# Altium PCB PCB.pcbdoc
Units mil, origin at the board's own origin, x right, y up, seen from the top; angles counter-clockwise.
Board outline 1800 x 1300 mil, 4 copper layers (Top Layer, Inner1, Inner2, Bottom Layer), stack 62.447 mil thick; 43 components, 24 nets, 128 pads, 70 vias.
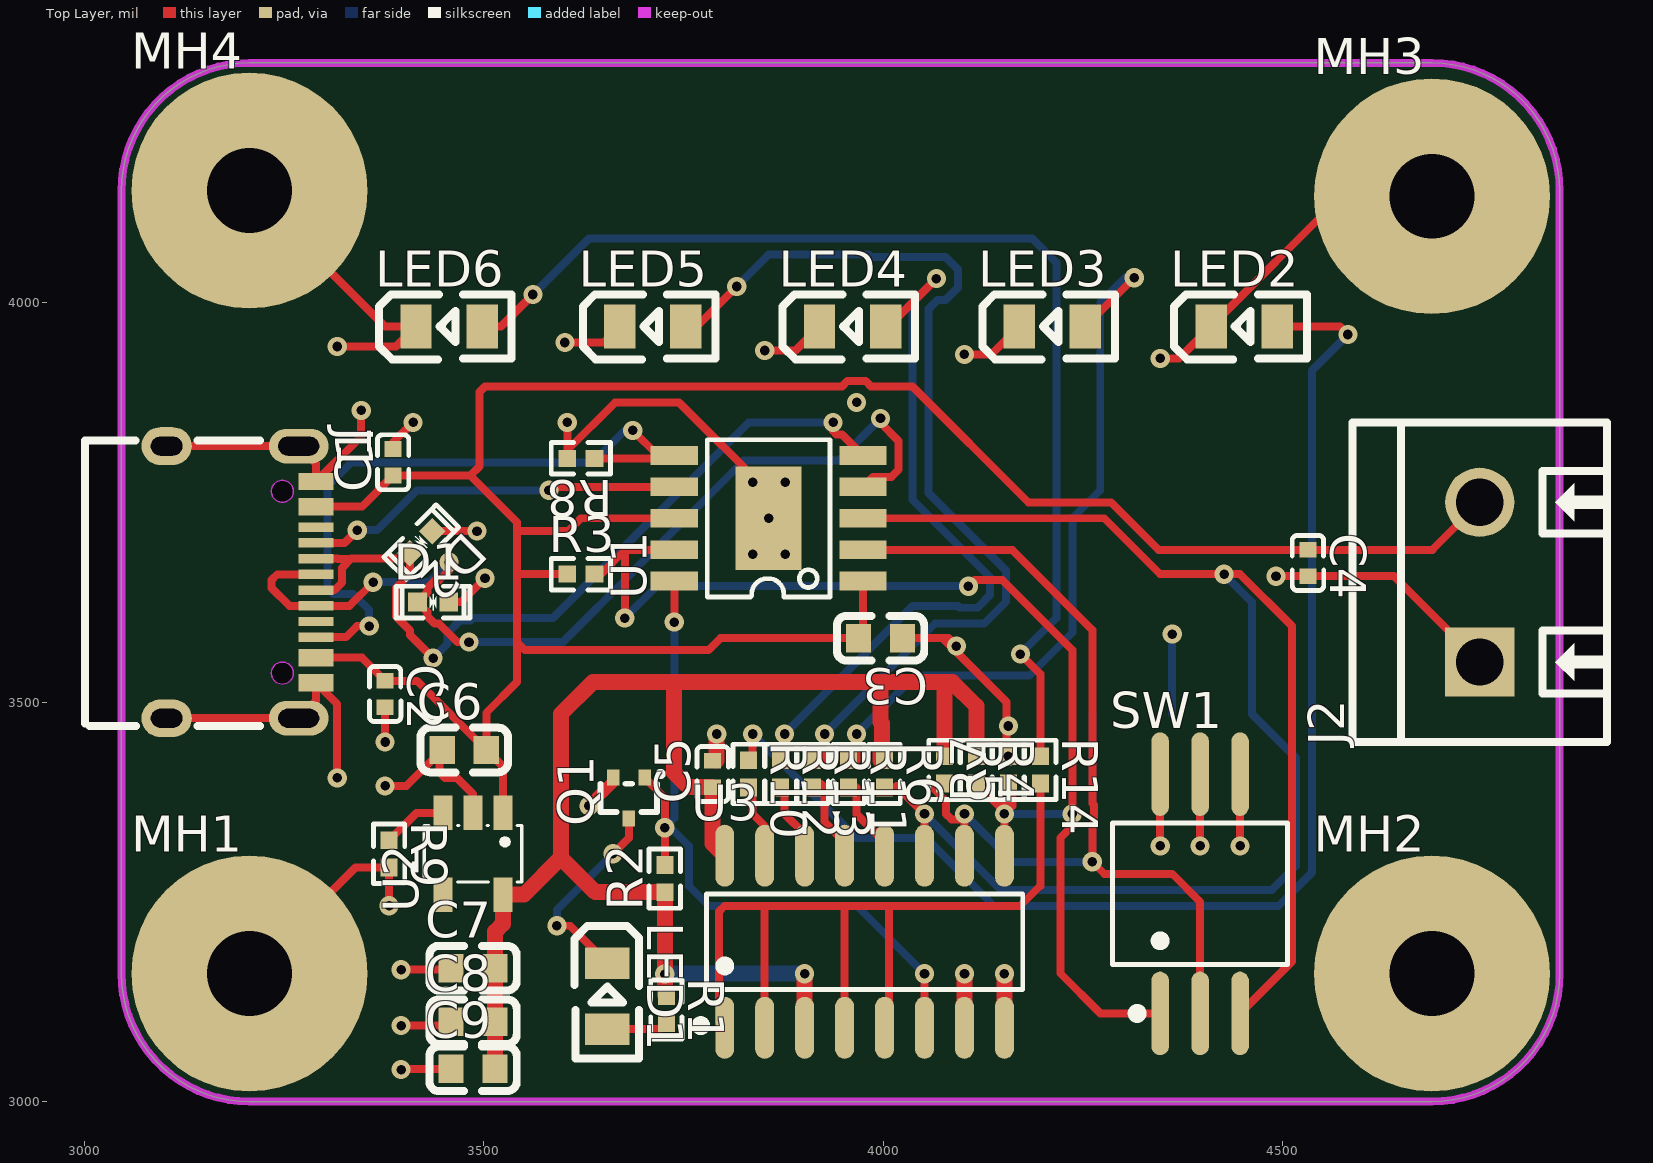
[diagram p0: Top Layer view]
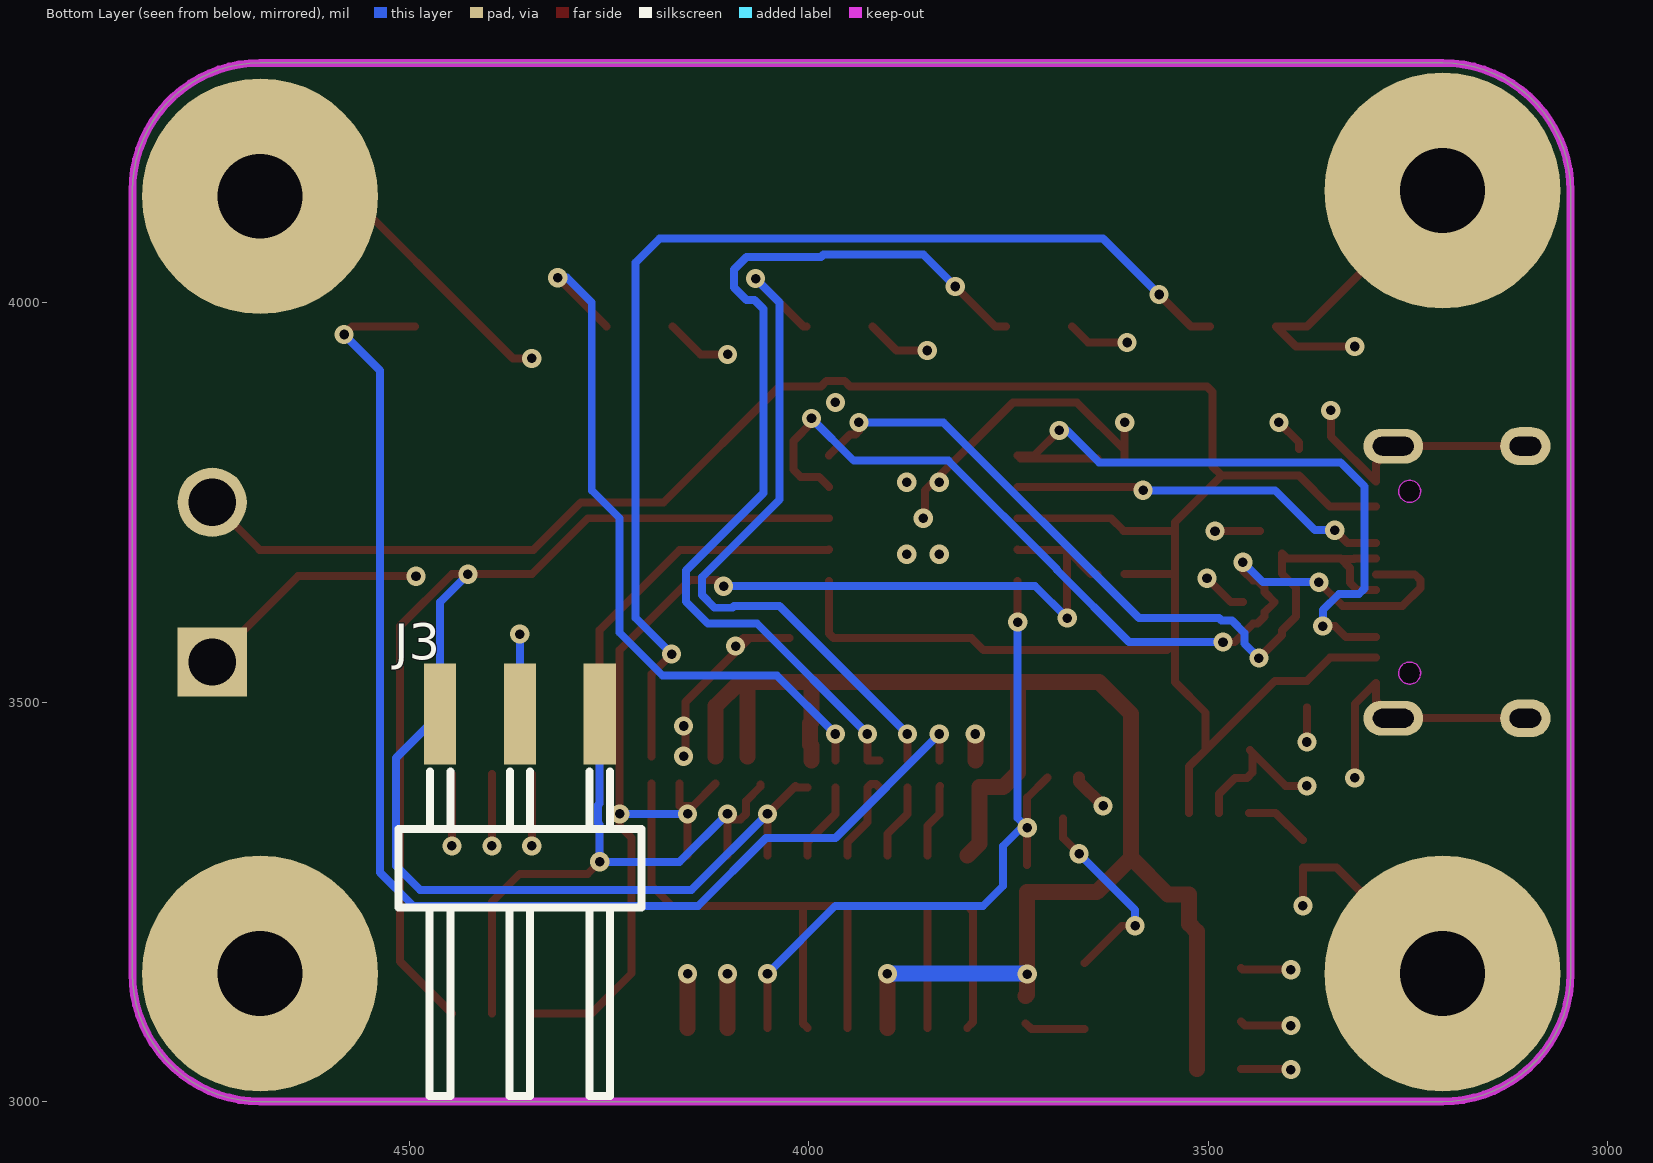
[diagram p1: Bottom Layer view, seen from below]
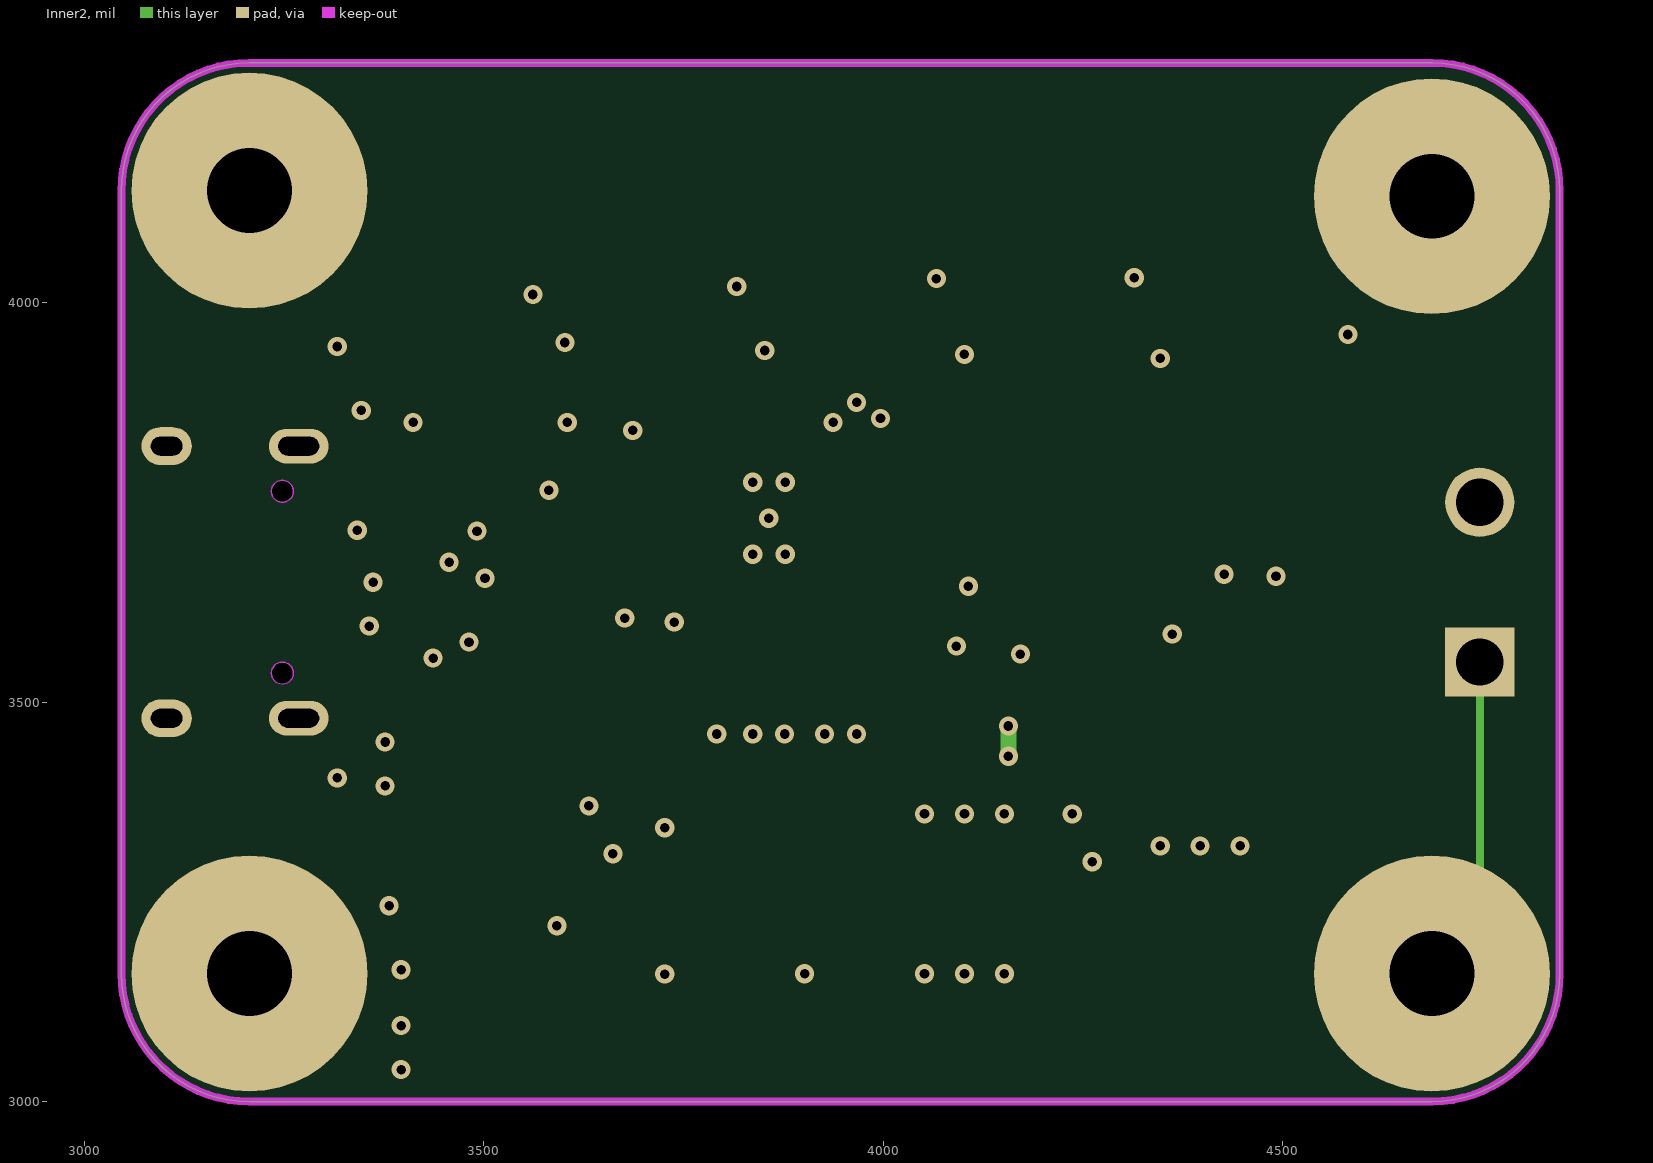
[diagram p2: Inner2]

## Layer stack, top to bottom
Top Layer: signal copper 1.378
Dielectric1: surface 8.283, 7628 RC49% 8.6mil, Dk 0
Inner1: signal copper 0.598
Dielectric2: surface 41.929, 1.1mm H/HOZ Copper, Dk 0
Inner2: signal copper 0.598
Dielectric3: surface 8.283, 7628 RC49% 8.6mil, Dk 0
Bottom Layer: signal copper 1.378

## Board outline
3206.88,4300 ccw(c3206.88,4140) 3046.88,4140 3046.88,3160 ccw(c3206.88,3160) 3206.88,3000 4686.88,3000 ccw(c4686.88,3160) 4846.88,3160 4846.88,4140 ccw(c4686.88,4140) 4686.88,4300

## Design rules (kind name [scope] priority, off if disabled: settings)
BoardOutlineClearance copperThickness1oz [All] p0: genericclearance=10 ignorepadtopadclearanceinfootprint=FALSE except(0: Arc-SplitContinuation Track-SplitContinuation SMDPad-SplitContinuation THPad-SplitContinuation Via-SplitContinuation Fill-SplitContinuation Poly-SplitContinuation Region-SplitContinuation Text-SplitContinuation)
BoardOutlineClearance copperThickness2oz [All] p0: genericclearance=10 ignorepadtopadclearanceinfootprint=FALSE except(0: Arc-SplitContinuation Track-SplitContinuation SMDPad-SplitContinuation THPad-SplitContinuation Via-SplitContinuation Fill-SplitContinuation Poly-SplitContinuation Region-SplitContinuation Text-SplitContinuation)
BoardOutlineClearance USBC_Clearance [All] p0: genericclearance=10 ignorepadtopadclearanceinfootprint=FALSE except(0: Arc-SplitContinuation Track-SplitContinuation SMDPad-SplitContinuation THPad-SplitContinuation Via-SplitContinuation Fill-SplitContinuation Poly-SplitContinuation Region-SplitContinuation Text-SplitContinuation)
BoardOutlineClearance otherClearance [All] p0: genericclearance=10 ignorepadtopadclearanceinfootprint=FALSE except(0: Arc-SplitContinuation Track-SplitContinuation SMDPad-SplitContinuation THPad-SplitContinuation Via-SplitContinuation Fill-SplitContinuation Poly-SplitContinuation Region-SplitContinuation Text-SplitContinuation)
Clearance copperThickness1oz [All] p1: gap=7 ignorepadtopadclearanceinfootprint=FALSE
Clearance copperThickness2oz [All] p1: gap=7 ignorepadtopadclearanceinfootprint=FALSE
Clearance USBC_Clearance [All] p1: gap=7 ignorepadtopadclearanceinfootprint=FALSE
Clearance otherClearance [All] p1: gap=7 ignorepadtopadclearanceinfootprint=FALSE
DiffPairsRouting differentialPair [All] p1: maxuncoupledlength=10 minlimit=6 maxlimit=Infinity mostfreqgap=6 toplayer_minwidth=6.2 toplayer_prefwidth=8 toplayer_maxwidth=10 bottomlayer_minwidth=6.2 bottomlayer_prefwidth=8 bottomlayer_maxwidth=10 midlayer1_minwidth=6.2 midlayer1_prefwidth=8 midlayer1_maxwidth=10 midlayer2_minwidth=6.2 midlayer2_prefwidth=8 midlayer2_maxwidth=10
PasteMaskExpansion pasteMaskExpansion [All] p1: expansion=0
PlaneConnect innerPlane [All] p1: planeconnectstyle=Relief reliefexpansion=20 reliefentries=4 reliefconductorwidth=10 reliefairgap=10
PolygonConnect copperRegion [All] p1: connectstyle=Relief reliefentries=4 reliefconductorwidth=10 polygonreliefangle="90 Angle" airgapwidth=10
RoutingVias viaSize [All] p1: viastyle="Through Hole" holewidth=12.0078 minholewidth=11.811 maxholewidth=248.0314 width=12.0078 minwidth=11.811 maxwidth=248.0314
SolderMaskExpansion solderMaskExpansion [IsVia] p1: useseparateexpansions=TRUE expansion=-1000 expansionbottom=-1000
SolderMaskExpansion solderMaskExpansion [All] p2: useseparateexpansions=TRUE expansion=2 expansionbottom=2
Width copperThickness1oz [All] p1: maxlimit=100 minlimit=10 preferedwidth=10
Width copperThickness2oz [All] p1: maxlimit=100 minlimit=8 preferedwidth=10

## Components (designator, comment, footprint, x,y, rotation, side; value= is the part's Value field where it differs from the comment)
C1 "100nF" C0402 3386.88,3800 r90 top
C2 "100nF" C0402 3376.88,3510 r270 top
C3 "1uF" C0603 3996.88,3580 r180 top
C4 "100nF" C0402 4531.88,3674 r270 top
C5 "100nF" C0402 3786.88,3410 r90 top
C6 "1uF" C0603 3475.88,3440 r0 top
C7 "1uF" C0603 3486.88,3167 r0 top
C8 "1uF" C0603 3486.88,3100.02 r0 top
C9 "1uF" C0603 3486.88,3041 r0 top
D1 "GG0402052R542P" D0402-BI 3436.88,3625 r0 top
D2 "GG0402052R542P" D0402-BI 3421.88,3700 r225 top
J1 "TYPE-C 16PIN 2MD(073)" USB-C-SMD_TYPE-C-16PIN-2MD-073 3196.88,3650 r270 top
J2 "MKDSN 1,5/ 2-5,08" CONN-TH_2P-P5.08_1729128 4746.88,3650 r90 top
J3 "HX PZ2.54-1x3P WT" HDR-SMD_3P-P2.54-H-M_KH-2.54PH-1X3P-L13.5-WT 4361.89,3485.01 r180 bottom
LED1 "KT-0805R" LED0805-R-RD 3654.88,3132 r270 top
LED2 "KT-0805G" LED0805-R-RD 4451.88,3970 r0 top
LED3 "KT-0805G" LED0805-R-RD 4211.88,3970 r0 top
LED4 "KT-0805G" LED0805-R-RD 3961.88,3970 r0 top
LED5 "KT-0805G" LED0805-R-RD 3711.88,3970 r0 top
LED6 "KT-0805G" LED0805-R-RD 3456.88,3970 r0 top
MH1 "" MH_7.5MMx2.7MM 3206.88,3160 r0 top
MH2 "" MH_7.5MMx2.7MM 4686.88,3160 r0 top
MH3 "" MH_7.5MMx2.7MM 4686.88,4133 r0 top
MH4 "" MH_7.5MMx2.7MM 3206.88,4140 r0 top
Q1 "2N7002T-7-F" SOT-523-3_L1.6-W0.8-P1.00-LS1.6-BR 3681.88,3380 r90 top
R1 "1kΩ" R0402 3728.88,3115 r270 top
R2 "10kΩ" R0402 3726.88,3279 r90 top
R3 "100kΩ" R0402 3621.88,3660 r0 top
R4 "10kΩ" R0402 4116.88,3415 r270 top
R5 "10kΩ" R0402 4076.88,3415 r270 top
R6 "10kΩ" R0402 4001.88,3410 r270 top
R7 "6.8kΩ" R0402 4156.88,3415 r90 top
R8 "1kΩ" R0402 3621.88,3805 r180 top
R9 "10kΩ" R0402 3381.88,3310 r270 top
R10 "1kΩ" R0402 3831.88,3410 r270 top
R11 "1kΩ" R0402 3956.88,3410 r270 top
R12 "1kΩ" R0402 3871.88,3410 r270 top
R13 "1kΩ" R0402 3911.88,3410 r270 top
R14 "1kΩ" R0402 4196.88,3415 r270 top
SW1 "DSHP03TS-S" SW-SMD_DSHP03TS-S 4396.87,3259.98 r0 top
U1 "CH224A" ESSOP-10_L4.9-W3.9-P1.0-LS6.0-TL-EP 3856.88,3730 r90 top
U2 "TPS70933DBVR" SOT-23-5_L3.0-W1.7-P0.95-LS2.8-BR 3486.87,3310.01 r90 top
U3 "MC14051BDR2G" SOIC-16_L9.9-W3.9-P1.27-LS6.0-BL 3976.93,3200 r0 top

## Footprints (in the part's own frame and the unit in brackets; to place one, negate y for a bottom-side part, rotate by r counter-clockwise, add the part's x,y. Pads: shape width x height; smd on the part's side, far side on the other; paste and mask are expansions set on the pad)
C0402 [mm]
  rect 0.5x0.54 smd paste+0 mask+0.051: 1(-0.42,0) 2(0.42,0)
  silkscreen extent -0.87,-0.5 0.87,0.5
C0603 [mm]
  rect 0.8x0.9 smd: 1(-0.7,0) 2(0.7,0)
  silkscreen extent -1.39,-0.71 1.39,0.71
CONN-TH_2P-P5.08_1729128 [mm]
  rect 2.2x2.2 hole 1.5: 1(-2.54,0)
  round 2.2 hole 1.5: 2(2.54,0)
  silkscreen extent -5.08,-4.05 5.08,4.05
D0402-BI [mm]
  rect 0.6x0.6 smd paste-100 mask+0.051: 1(-0.5,0) 2(0.5,0)
  silkscreen extent -1.18,-0.5 1.17,0.51
ESSOP-10_L4.9-W3.9-P1.0-LS6.0-TL-EP [mm]
  rect 0.6x1.5 smd paste+0 mask+0.05: 1(-2,-3) 2(-1,-3) 3(0,-3) 4(1,-3) 5(2,-3) 6(2,3) 7(1,3) 8(0,3) 9(-1,3) 10(-2,3)
  rect 3.3x2.1 smd paste+0 mask+0.05: 11(0,0)
  silkscreen extent -2.5,-1.95 2.5,1.95
HDR-SMD_3P-P2.54-H-M_KH-2.54PH-1X3P-L13.5-WT [mm]
  rect 1.02x3.2 smd paste+0 mask+0.05: 1(-2.54,0) 2(0,0) 3(2.54,0)
  silkscreen extent -3.86,-12.15 3.87,-1.83
LED0805-R-RD [mm]
  rect 1x1.4 smd: 1(1.05,0) 2(-1.05,0)
  silkscreen extent -2.22,-1.04 1.99,1.01
MH_7.5MMx2.7MM [mm]
  round 7.5 hole 2.7: 1(0,0)
R0402 [mm]
  rect 0.566x0.54 smd paste-100 mask+0.051: 1(-0.433,0) 2(0.433,0)
  silkscreen extent -0.94,-0.5 0.94,0.5
SOIC-16_L9.9-W3.9-P1.27-LS6.0-BL [mil]
  oval 23.7x77.6 smd: 1(-175,-107.7) 2(-125,-107.7) 3(-75,-107.7) 4(-25,-107.7) 5(25,-107.7) 6(75,-107.7) 7(125,-107.7) 8(175,-107.7) 9(175,107.7) 10(125,107.7) 11(75,107.7) 12(25,107.7) 13(-25,107.7) 14(-75,107.7) 15(-125,107.7) 16(-175,107.7)
  silkscreen extent -211,-111 198,60
SOT-23-5_L3.0-W1.7-P0.95-LS2.8-BR [mm]
  rect 1.1x0.6 smd: 1(1.3,-0.95) 2(1.3,0) 3(1.3,0.95) 4(-1.3,0.95) 5(-1.3,-0.95)
  silkscreen extent -0.9,-1.55 0.9,1.55
SOT-523-3_L1.6-W0.8-P1.00-LS1.6-BR [mm]
  rect 0.51x0.4 smd: 1(0.65,-0.5) 2(0.65,0.5) 3(-0.65,0)
  silkscreen extent -0.45,-1.08 0.83,0.9
SW-SMD_DSHP03TS-S [mm]
  oval 0.56x2.655 smd: 1(-1.27,-3.803) 2(0,-3.803) 3(1.27,-3.803) 4(1.27,3.803) 5(0,3.803) 6(-1.27,3.803)
  silkscreen extent -2.78,-3.95 2.78,2.25
USB-C-SMD_TYPE-C-16PIN-2MD-073 [mm]
  oval 1.1x1.9 hole 0.6 slot 1.3 at 90 deg paste+0 mask+0.05: 13(-4.325,1.825) 14(4.325,1.825)
  oval 1.2x1.6 hole 0.6 slot 1 at 90 deg paste+0 mask+0.05: 13(-4.325,-2.375) 14(4.325,-2.375)
  rect 0.55x1.1 smd paste+0 mask+0.05: A1B12(-3.2,2.375) A4B9(-2.4,2.375) B1A12(3.2,2.375) B4A9(2.4,2.375)
  rect 0.3x1.1 smd paste+0 mask+0.05: A5(-1.25,2.375) A6(-0.25,2.375) A7(0.25,2.375) A8(1.25,2.375) B5(1.75,2.375) B6(0.75,2.375) B7(-0.75,2.375) B8(-1.75,2.375)
  Board Outline Layer circle w0.003: c-2.89,1.305 r0.35
  Board Outline Layer circle w0.003: c2.89,1.305 r0.35
  Board Outline Layer region: -2.89,1.655 -2.738,1.62 -2.616,1.523 -2.549,1.383 -2.549,1.227 -2.616,1.087 -2.738,0.99 -2.89,0.955 -2.89,0.955 -3.042,0.99 -3.164,1.087 -3.231,1.227 -3.231,1.383 -3.164,1.523 -3.042,1.62 -2.89,1.655
  Board Outline Layer region: -2.89,1.655 -2.812,1.646 -2.738,1.62 -2.672,1.579 -2.616,1.523 -2.575,1.457 -2.549,1.383 -2.54,1.305 -2.549,1.227 -2.575,1.153 -2.616,1.087 -2.672,1.031 -2.738,0.99 -2.812,0.964 -2.89,0.955 -2.968,0.964 -3.042,0.99 -3.108,1.031 -3.164,1.087 -3.205,1.153 -3.231,1.227 -3.24,1.305 -3.231,1.383 -3.205,1.457 -3.164,1.523 -3.108,1.579 -3.042,1.62 -2.968,1.646
  Board Outline Layer region: 2.89,1.655 3.042,1.62 3.164,1.523 3.231,1.383 3.231,1.227 3.164,1.087 3.042,0.99 2.89,0.955 2.89,0.955 2.738,0.99 2.616,1.087 2.549,1.227 2.549,1.383 2.616,1.523 2.738,1.62 2.89,1.655
  Board Outline Layer region: 2.89,1.655 2.968,1.646 3.042,1.62 3.108,1.579 3.164,1.523 3.205,1.457 3.231,1.383 3.24,1.305 3.231,1.227 3.205,1.153 3.164,1.087 3.108,1.031 3.042,0.99 2.968,0.964 2.89,0.955 2.812,0.964 2.738,0.99 2.672,1.031 2.616,1.087 2.575,1.153 2.549,1.227 2.54,1.305 2.549,1.383 2.575,1.457 2.616,1.523 2.672,1.579 2.738,1.62 2.812,1.646
  Multi-Layer board cut-out: -2.89,1.655 -2.738,1.62 -2.616,1.523 -2.549,1.383 -2.549,1.227 -2.616,1.087 -2.738,0.99 -2.89,0.955 -2.89,0.955 -3.042,0.99 -3.164,1.087 -3.231,1.227 -3.231,1.383 -3.164,1.523 -3.042,1.62 -2.89,1.655
  Multi-Layer board cut-out: 2.89,1.655 3.042,1.62 3.164,1.523 3.231,1.383 3.231,1.227 3.164,1.087 3.042,0.99 2.89,0.955 2.89,0.955 2.738,0.99 2.616,1.087 2.549,1.227 2.549,1.383 2.616,1.523 2.738,1.62 2.89,1.655
  silkscreen extent -4.5,-4.97 4.57,0.6

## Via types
v1: diameter 24.02, hole 12, Top Layer to Bottom Layer, 70 vias

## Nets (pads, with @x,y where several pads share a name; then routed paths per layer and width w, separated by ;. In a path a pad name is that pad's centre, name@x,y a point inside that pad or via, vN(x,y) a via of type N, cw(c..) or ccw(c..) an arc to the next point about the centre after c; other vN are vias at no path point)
$1N47: LED1.1 R1.2 | length 77
  Top Layer w10: LED1.1 3721.57,3090.65 R1.2
$1N48: LED1.2 Q1.3 | length 254
  Top Layer w10: v1(3591.88,3220) 3608.23,3220 LED1.2 ; v1(3661.88,3310) 3681.89,3330.01 Q1.3
  Bottom Layer w10: v1(3591.88,3220) 3591.88,3240 v1(3661.88,3310)
$1N55: LED2.1 R10.1 | length 1624
  Top Layer w10: R10.1@3836.88,3427.04 v1(3836.88,3460) ; LED2.1 4571.88,3970 v1(4581.88,3960)
  Bottom Layer w10: v1(3836.88,3460) 3966.88,3330 4053.64,3330 4138.64,3245 4495.17,3245 4536.88,3286.72 4536.88,3915 v1(4581.88,3960)
$1N56: LED3.1 R11.1 | length 925
  Top Layer w10: R11.1@3966.88,3427.04 v1(3966.88,3460) ; LED3.1 v1(4314.35,4031.11)
  Bottom Layer w10: v1(3966.88,3460) 4039.88,3532.99 4183.07,3532.99 4236.88,3586.81 4236.88,3730 4271.88,3765 4271.88,4000 4303,4031.11 v1(4314.35,4031.11)
$1N57: LED4.1 R12.1 | length 900.9
  Top Layer w10: R12.1@3876.88,3427.04 v1(3876.88,3460) ; LED4.1 4006.88,3970 v1(4066.88,4030)
  Bottom Layer w10: v1(3876.88,3460) 4036.88,3620 4093.69,3620 4095.7,3617.99 4118.07,3617.99 4133.89,3633.81 4133.89,3656.19 4036.88,3753.19 4036.88,4000 v1(4066.88,4030)
$1N58: LED5.1 R13.1 | length 1206.2
  Top Layer w10: LED5.1 3766.88,3970 v1(3816.88,4020) ; R13.1 3926.88,3427.04 v1(3926.88,3460)
  Bottom Layer w10: v1(3816.88,4020) 3856.88,4060 3981.88,4060 3984.88,4057.01 4078.07,4057.01 4093.89,4041.19 4093.89,4018.81 4078.07,4002.99 4068.16,4002.99 4056.88,3991.72 4056.88,3761.48 4153.89,3664.47 4153.89,3625.53 4126.36,3597.99 4064.88,3597.99 v1(3926.88,3460)
$1N59: LED6.1 R14.1 | length 1423.6
  Top Layer w10: LED6.1 3521.88,3970 v1(3561.88,4010) ; v1(4171.88,3560) 4196.88,3535 R14.1
  Bottom Layer w10: v1(3561.88,4010) 3631.88,4080 4186.88,4080 4216.88,4050 4216.88,3605 v1(4171.88,3560)
$1N79: R10.2 U3.15 | length 93.9
  Top Layer w10: R10.2@3835.88,3394.96 3836.88,3393.96 3836.88,3360 3851.93,3344.95 U3.15
$1N80: R11.2 U3.12 | length 99.8
  Top Layer w10: R11.2@3966.88,3392.96 3966.88,3360 4001.93,3324.95 U3.12
$1N81: R12.2 U3.14 | length 95.6
  Top Layer w10: R12.2@3876.88,3392.96 3876.88,3360 3901.93,3334.95 U3.14
$1N82: R13.2 U3.13 | length 114.3
  Top Layer w10: R13.2 3916.28,3397.35 3922.49,3397.35 3926.88,3392.96 3926.88,3350 3951.93,3324.95 U3.13
$1N83: R14.2 U3.1 U3.2 U3.4 U3.5 | length 1152.8
  Top Layer w10: U3.1 3794.81,3099.41 3794.81,3237.93 3801.88,3245 3850.92,3245 ; U3.2 3851.93,3243.99 3850.92,3245 ; U3.4 3951.93,3244.73 3951.66,3245 ; U3.5 4007.46,3097.83 4007.46,3245 ; R14.2 4196.88,3270 4171.88,3245 4007.46,3245 ; 3850.92,3245 3951.66,3245 ; 3951.66,3245 4007.46,3245
+3V3: C5.1 C7.2 C8.2 C9.2 R1.1 R2.1 R4.1 R5.1 R6.1 U2.5 U3.3 U3.16 | length 2081.7
  Top Layer w20: C9.2 C8.2 C7.2 3514.44,3212.56 3524.27,3222.39 U2.5 3550.71,3258.82 3596.88,3305 ; R1.1 3726.88,3134.04 v1(3726.88,3159.51) R2.1 3639.92,3261.96 3596.88,3305 ; U3.16 3786.88,3322.74 C5.1 3756.88,3393.46 3738.61,3411.73 3738.61,3523.22 3736.84,3525 ; U3.3 v1(3901.93,3160) ; R6.1@3996.88,3427.04 3996.88,3444.73 3998.89,3446.74 3998.89,3473.26 3996.88,3475.27 3996.88,3524.62 3996.5,3525 ; R5.1 4076.88,3524.52 4076.41,3525 ; R4.1 4116.88,3495 4086.88,3525 4076.41,3525 ; 3596.88,3305 3596.88,3485 3636.88,3525 3736.84,3525 ; 3736.84,3525 3996.5,3525 ; 3996.5,3525 4076.41,3525
  Bottom Layer w20: v1@3726.88,3160 v1(3901.93,3160)
+V_USB: C1.1 C2.1 C3.2 C4.1 C6.2 J1.A4B9 J1.B4A9 J2.2 R3.1 U1.1 U1.8 U2.1 | length 3198.7
  Top Layer w10: J1.B4A9 3347.92,3555.51 C2.1 3416.9,3526.54 C6.2 ; J1.A4B9 3347.91,3744.49 C1.1 3483.42,3783.46 ; U2.1 3524.27,3419.17 C6.2 ; R3.1 3543.42,3660 3541.88,3661.54 ; U1.8 3621.88,3730 3606.12,3714.24 3541.88,3714.24 ; U1.1 3975,3585.68 C3.2 3796.88,3580 3781.88,3565 3551.62,3565 3541.88,3574.74 ; J2.2 4687.42,3690.54 C4.1 4344.63,3690.54 4285.17,3750 4181.88,3750 4036.88,3895 3985.08,3895 3978.07,3902.01 3955.7,3902.01 3948.69,3895 3501.88,3895 3494.81,3887.93 3494.81,3794.85 3483.42,3783.46 ; 3483.42,3783.46 3541.88,3725 3541.88,3714.24 ; C6.2 3503.44,3486.56 3541.88,3525 3541.88,3574.74 ; 3541.88,3574.74 3541.88,3661.54 ; 3541.88,3661.54 3541.88,3714.24
CC1: J1.A5 U1.7 | length 477.4
  Top Layer w10: J1.A5 3326.09,3699.2 v1(3341.88,3715) ; v1(3581.88,3765) 3586.26,3769.37 U1.7
  Bottom Layer w10: v1(3341.88,3715) 3366.88,3715 3416.88,3765 v1(3581.88,3765)
CC2: J1.B5 R8.1 U1.6 | length 860.8
  Top Layer w10: J1.B5 3327.98,3581.09 3341.88,3595 v1(3356.88,3595) ; R8.1 3735.04,3805 U1.6 3718.14,3808.74 v1(3686.88,3840)
  Bottom Layer w10: v1(3356.88,3595) 3356.88,3615 3336.88,3635 3311.88,3635 3304.81,3642.07 3304.81,3770 3334.81,3800 3636.88,3800 3676.88,3840 v1(3686.88,3840)
CFG1: R3.2 R4.2 R7.1 SW1.1 U1.9 U3.9 | length 1591.8
  Top Layer w10: R3.2 3646.88,3660 3676.88,3690 ; v1(3676.88,3605) 3676.88,3690 ; U1.9 3738.14,3690 3676.88,3690 ; v1(4106.88,3645) 4114.38,3652.5 4149.38,3652.5 4236.88,3565 v1(4236.88,3360) 4236.88,3345 4221.88,3330 4221.88,3160.55 4272.16,3110.28 SW1.1 ; R4.2 4144.89,3369.95 4161.88,3369.95 R7.1@4161.88,3397.96 ; U3.9 v1(4151.93,3360)
  Bottom Layer w10: v1(3676.88,3605) 3716.88,3645 v1(4106.88,3645) ; v1(4151.93,3360) v1(4236.88,3360)
CFG2_SCL: J3.3 R5.2 SW1.2 U1.2 U3.10 | length 1412.4
  Top Layer w10: U1.2 3975.63,3690 4161.88,3690 4261.88,3590 4261.88,3373.19 4263.89,3371.19 4263.89,3348.81 4261.88,3346.81 v1(4261.88,3300) 4276.88,3285 4361.88,3285 4396.87,3250.02 SW1.2 ; 4060.88,3396.96 4060.88,3393.98 4078.94,3375.93 4078.94,3360 4085.67,3353.27 4095.19,3353.27 v1(4101.93,3360) U3.10
  Bottom Layer w10: v1(4101.93,3360) 4161.93,3300 v1(4261.88,3300) 4261.89,3346.82 4263.89,3348.81 4263.89,3371.19 4261.89,3373.18 J3.3
CFG3_SDA: J3.1 R6.2 SW1.3 U1.3 U3.11 | length 2141.2
  Top Layer w10: U1.3 4276.88,3730 4346.88,3660 v1(4426.88,3660) 4446.88,3660 4511.88,3595 4511.88,3175.29 SW1.3 ; R6.2 4014.8,3392.96 4016.88,3395.05 v1(4051.93,3360) U3.11
  Bottom Layer w10: v1(4051.93,3360) 4146.93,3265 4486.88,3265 4516.88,3295 4516.88,3430.02 J3.1 4461.89,3624.99 v1(4426.88,3660)
EN_3V3: R9.1 U2.3 | length 81.7
  Top Layer w10: R9.1 3416.04,3361.19 U2.3
GND: C1.2 C2.2 C3.1 C4.2 C5.2 C6.1 C7.1 C8.1 C9.1 D1.2 D2.1 J1.13 J1.14 J1.A1B12 J1.B1A12 J2.1 J3.2 LED2.2 LED3.2 LED4.2 LED5.2 LED6.2 MH1.1 MH2.1 MH3.1 MH4.1 Q1.2 R7.2 R8.2 R9.2 SW1.4 SW1.5 SW1.6 U1.11 U2.2 U3.7 U3.8 | length 4637.6
  Top Layer w10: J1.14@3103.38,3479.72 3268.74,3479.72 3290.39,3501.37 J1.B1A12 3316.88,3497.52 v1(3316.88,3405) ; J1.13@3103.38,3820.27 3268.74,3820.27 3290.39,3798.62 J1.A1B12 3346.88,3832.48 v1(3346.88,3865) ; MH1.1 3339.84,3292.96 R9.2 v1(3381.88,3245) ; MH4.1 3376.89,3970 LED6.2 3390.53,3945 v1(3316.88,3945) ; v1(3376.88,3395) 3403.32,3395 C6.1@3444.81,3436.49 ; v1(3376.88,3450) C2.2 ; C1.2 3386.88,3825 v1(3411.88,3850) ; v1(3396.88,3040) 3397.88,3041 C9.1 ; v1(3396.88,3095) 3454.3,3095 C8.1 ; v1(3396.88,3165) 3457.32,3165 C7.1 ; D2.1 v1(3491.88,3713.92) ; C6.1 C6.1@3444.81,3436.49 ; D1.2 3471.88,3625 v1(3501.88,3655) ; U2.2 3486.87,3385.01 3466.88,3405 3451.88,3405 3444.81,3412.07 C6.1@3444.81,3436.49 ; v1(3601.88,3950) 3650.53,3950 LED5.2 ; R8.2 R8.2@3604.84,3815 ; v1(3604.84,3850) R8.2@3604.84,3815 ; v1(3851.88,3940) 3890.53,3940 LED4.2 ; v1(3856.88,3730) 3854.84,3732.04 3854.84,3765 3744.84,3875 3664.84,3875 R8.2@3604.84,3815 ; v1(4091.88,3570) 4081.88,3580 C3.1 4074.44,3580 4154.44,3500 4154.44,3434.48 v1(4156.88,3432.04) ; v1(4101.88,3935) 4135.53,3935 LED3.2 ; v1(4346.88,3320) SW1.6 ; v1(4346.88,3930) 4370.53,3930 LED2.2 4573.54,4133 MH3.1 ; v1(4396.87,3320) SW1.5 ; v1(4446.88,3320) SW1.4 ; v1(4491.88,3657.46) C4.2 4639.42,3657.46 J2.1
  Top Layer w15: v1(3631.88,3370) 3662.2,3400.32 Q1.2
  Top Layer w20: C5.2@3791.88,3426.54 v1(3791.88,3460) ; U3.7 v1(4101.93,3160) ; U3.8 v1(4151.93,3160)
  Inner2 w10: MH2.1 4746.88,3220 J2.1
  Inner2 w20: v1(4156.88,3432.04) v1(4156.88,3470)
  Bottom Layer w10: J3.2 v1(4361.89,3585)
  other v1: 3836.88,3685 3877.75,3684.9 3836.88,3775 3877.75,3775 3966.88,3875
PG: Q1.1 R2.2 U1.10 U3.6 | length 931.3
  Top Layer w10: Q1.1 3726.88,3380.28 v1(3726.88,3342.66) R2.2 ; v1(3738.78,3600) U1.10 ; U3.6 v1(4051.93,3160)
  Bottom Layer w10: v1(3738.78,3600) 3738.78,3354.55 v1(3726.88,3342.66) 3734.23,3342.66 3756.88,3320 3756.88,3270 3781.98,3244.9 3967.02,3244.9 v1(4051.93,3160)
USB_N: D2.2 J1.A7 J1.B7 U1.5 | length 1040.5
  Top Layer w10: J1.A7 3313.81,3640.16 3323.04,3649.38 3323.04,3667.87 3334.37,3679.2 ; J1.B7 3317.48,3679.53 3317.8,3679.2 3334.37,3679.2 ; v1(3436.88,3555) 3407.96,3583.92 3407.96,3589.4 3390.39,3606.98 3390.39,3643.02 3407.96,3660.6 D2.2 3401.41,3679.53 3334.69,3679.53 3334.37,3679.2 ; v1(3937.49,3850) 3937.49,3839.39 3941.88,3835 3948.74,3835 U1.5
  Bottom Layer w10: v1(3436.88,3555) 3454.88,3572.99 3454.88,3586.19 3470.7,3602.01 3483.89,3602.01 3486.88,3605 3586.88,3605 3831.88,3850 v1(3937.49,3850)
USB_P: D1.1 J1.A6 J1.B6 U1.4 | length 1239.1
  Top Layer w10: J1.A6 3241.88,3659.84 3234.81,3652.77 3234.81,3642.77 3257.11,3620.47 J1.B6 3332.36,3620.47 v1(3361.88,3650) ; v1(3456.88,3675) 3456.88,3664.68 3444.01,3651.81 3438.54,3651.81 3429.76,3643.02 3429.76,3637.56 D1.1 3429.76,3612.44 3429.76,3606.98 3438.54,3598.19 3444.01,3598.19 3467.2,3575 v1(3481.88,3575) ; U1.4 3987.56,3781.93 4010.74,3781.93 4019.53,3790.72 4019.53,3826.77 3996.88,3849.41 v1(3996.88,3855)
  Bottom Layer w10: v1(3361.88,3650) 3431.88,3650 v1(3456.88,3675) ; v1(3481.88,3575) 3599.38,3575 3689.38,3665 3689.38,3665.69 3825.7,3802.01 3943.89,3802.01 v1(3996.88,3855)
pads on no net: J1.A8 J1.B8 U2.4

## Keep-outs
Board Outline Layer:
  the board outline again, w10

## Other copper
Top Layer:
  pour cut-out: 3201.88,3865 3201.88,3430 3336.88,3430 3336.88,3865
